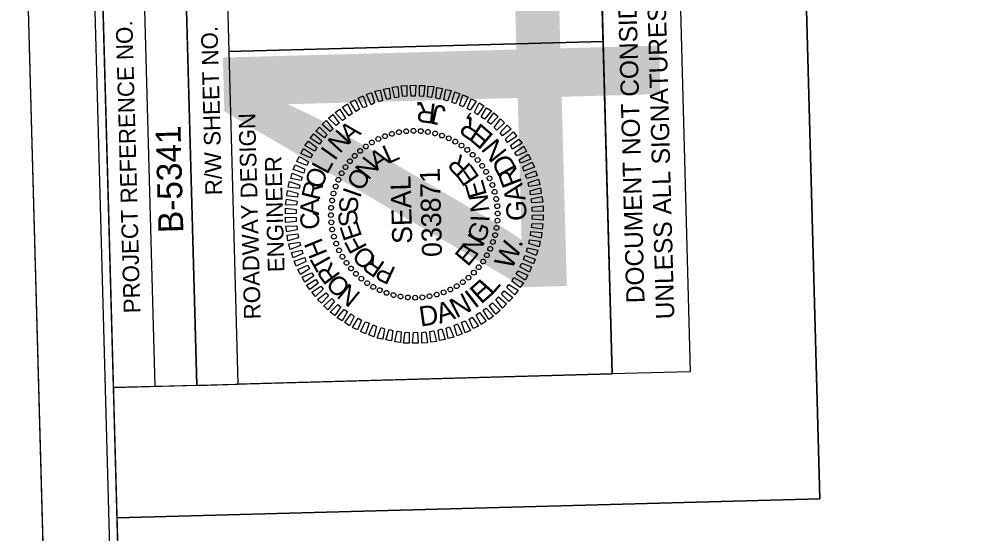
# Model space of a CAD drawing. Extents: x 1835283 to 1836442, y 993567 to 997230.
# Drawn here: x 1835301.2 to 1835586.3, y 995091.9 to 995246.4 of the extents above; entities that cross this region are included whole.
import ezdxf

# ---------------------------------------------------------------- set-up
doc = ezdxf.new("R2010")
doc.units = 0
for name, color, linetype in [('Sheet Clip Boundary CELL', 7, 'Continuous'), ('Sheet Cutting Line CELL', 7, 'Continuous'), ('Sheet Data Field CELL', 7, 'Continuous'), ('Sheet Layout Plan Border', 7, 'Continuous'), ('Sheet PE Seal Cell', 7, 'Continuous'), ('Sheet Plan CELL', 7, 'Continuous'), ('Sheet Plan Layout CELL', 7, 'Continuous'), ('Sheet Plot Border Inside CELL', 7, 'Continuous'), ('Sheet Plot Border Outside CELL', 7, 'Continuous'), ('Sheet Sticker Exception Certification CELL', 7, 'Continuous')]:
    doc.layers.add(name, color=color, linetype=linetype)

msp = doc.modelspace()

# ---------------------------------------------------------------- linework, layer by layer
at = {"layer": 'Sheet Clip Boundary CELL'}
msp.add_lwpolyline([(1836414.25, 993881.51), (1836374.18, 995348.6), (1835535.98, 995325.71), (1835542.09, 995102.18), (1835330.68, 995096.4), (1835364.64, 993852.84)], close=True, dxfattribs=at)
msp.add_lwpolyline([(1836414.25, 993881.51), (1836374.18, 995348.6), (1835535.98, 995325.71), (1835542.09, 995102.18), (1835330.68, 995096.4), (1835364.64, 993852.84)], close=True, dxfattribs=at)
at = {"layer": 'Sheet Cutting Line CELL'}
msp.add_line((1835301.2, 995351.94), (1835347.16, 993669.07), dxfattribs=at)
at = {"layer": 'Sheet Layout Plan Border'}
msp.add_lwpolyline([(1836414.25, 993881.51), (1836374.18, 995348.6), (1835535.98, 995325.71), (1835542.09, 995102.18), (1835330.68, 995096.4), (1835364.64, 993852.84)], close=True, dxfattribs=at)
msp.add_lwpolyline([(1836414.25, 993881.51), (1836374.18, 995348.6), (1835535.98, 995325.71), (1835542.09, 995102.18), (1835330.68, 995096.4), (1835364.64, 993852.84)], close=True, dxfattribs=at)
at = {"layer": 'Sheet PE Seal Cell'}
for p, q in [((1835409.28, 995210.37), (1835409.28, 995210.37)), ((1835411.25, 995211.22), (1835411.25, 995211.22)), ((1835413.34, 995211.88), (1835413.34, 995211.88)), ((1835415.52, 995212.34), (1835415.52, 995212.34)), ((1835417.67, 995212.7), (1835417.67, 995212.7)), ((1835419.86, 995212.81), (1835419.86, 995212.81)), ((1835422.07, 995212.72), (1835422.07, 995212.72)), ((1835424.22, 995212.43), (1835424.22, 995212.43)), ((1835426.34, 995212.04), (1835426.34, 995212.04)), ((1835428.45, 995211.39), (1835428.45, 995211.39)), ((1835430.48, 995210.55), (1835430.48, 995210.55)), ((1835405.49, 995208.12), (1835405.49, 995208.12)), ((1835407.35, 995209.32), (1835407.35, 995209.32)), ((1835432.46, 995209.6), (1835432.46, 995209.6)), ((1835434.29, 995208.4), (1835434.29, 995208.4)), ((1835402.16, 995205.27), (1835402.16, 995205.27)), ((1835403.77, 995206.82), (1835403.77, 995206.82)), ((1835436.07, 995207.1), (1835436.07, 995207.1)), ((1835437.67, 995205.64), (1835437.67, 995205.64)), ((1835399.4, 995201.9), (1835399.4, 995201.9)), ((1835400.7, 995203.68), (1835400.7, 995203.68)), ((1835439.21, 995204.03), (1835439.21, 995204.03)), ((1835440.51, 995202.32), (1835440.51, 995202.32)), ((1835398.2, 995200.06), (1835398.2, 995200.06)), ((1835441.71, 995200.45), (1835441.71, 995200.45)), ((1835396.41, 995196.06), (1835396.41, 995196.06)), ((1835397.26, 995198.09), (1835397.26, 995198.09)), ((1835442.76, 995198.53), (1835442.76, 995198.53)), ((1835443.62, 995196.55), (1835443.62, 995196.55)), ((1835395.77, 995193.94), (1835395.77, 995193.94)), ((1835444.27, 995194.47), (1835444.27, 995194.47)), ((1835395.38, 995191.83), (1835395.38, 995191.83)), ((1835444.73, 995192.28), (1835444.73, 995192.28)), ((1835395, 995187.47), (1835395, 995187.47)), ((1835395.09, 995189.67), (1835395.09, 995189.67)), ((1835420.1, 995187.71), (1835420.1, 995187.71)), ((1835445.09, 995190.14), (1835445.09, 995190.14)), ((1835445.2, 995187.94), (1835445.2, 995187.94)), ((1835395.11, 995185.27), (1835395.11, 995185.27)), ((1835445.11, 995185.74), (1835445.11, 995185.74)), ((1835395.46, 995183.13), (1835395.46, 995183.13)), ((1835444.82, 995183.58), (1835444.82, 995183.58)), ((1835395.92, 995180.94), (1835395.92, 995180.94)), ((1835396.58, 995178.86), (1835396.58, 995178.86)), ((1835443.79, 995179.35), (1835443.79, 995179.35)), ((1835444.43, 995181.47), (1835444.43, 995181.47)), ((1835397.44, 995176.88), (1835397.44, 995176.88)), ((1835442.94, 995177.33), (1835442.94, 995177.33)), ((1835398.49, 995174.96), (1835398.49, 995174.96)), ((1835399.69, 995173.09), (1835399.69, 995173.09)), ((1835440.79, 995173.52), (1835440.79, 995173.52)), ((1835441.99, 995175.35), (1835441.99, 995175.35)), ((1835400.99, 995171.38), (1835400.99, 995171.38)), ((1835439.49, 995171.73), (1835439.49, 995171.73)), ((1835402.53, 995169.77), (1835402.53, 995169.77)), ((1835404.12, 995168.31), (1835404.12, 995168.31)), ((1835436.43, 995168.6), (1835436.43, 995168.6)), ((1835438.03, 995170.14), (1835438.03, 995170.14)), ((1835405.91, 995167.01), (1835405.91, 995167.01)), ((1835407.74, 995165.81), (1835407.74, 995165.81)), ((1835409.72, 995164.86), (1835409.72, 995164.86)), ((1835430.92, 995165.04), (1835430.92, 995165.04)), ((1835432.84, 995166.1), (1835432.84, 995166.1)), ((1835434.71, 995167.3), (1835434.71, 995167.3)), ((1835411.74, 995164.02), (1835411.74, 995164.02)), ((1835413.86, 995163.38), (1835413.86, 995163.38)), ((1835415.97, 995162.98), (1835415.97, 995162.98)), ((1835418.13, 995162.69), (1835418.13, 995162.69)), ((1835420.33, 995162.6), (1835420.33, 995162.6)), ((1835422.53, 995162.71), (1835422.53, 995162.71)), ((1835424.67, 995163.07), (1835424.67, 995163.07)), ((1835426.86, 995163.53), (1835426.86, 995163.53)), ((1835428.94, 995164.19), (1835428.94, 995164.19))]:
    msp.add_line(p, q, dxfattribs=at)
for points in [[(1835409.47, 995221.53), (1835408.23, 995224.7), (1835409.88, 995225.04), (1835410.51, 995221.91)], [(1835411.85, 995222.19), (1835410.82, 995225.32), (1835412.51, 995225.66), (1835412.9, 995222.52)], [(1835414.24, 995222.71), (1835413.45, 995225.94), (1835415.15, 995226.14), (1835415.43, 995222.94)], [(1835416.63, 995223.08), (1835416.14, 995226.31), (1835417.84, 995226.46), (1835417.83, 995223.21)], [(1835419.13, 995223.19), (1835418.89, 995226.44), (1835420.59, 995226.48), (1835420.33, 995223.23)], [(1835421.63, 995223.21), (1835421.64, 995226.46), (1835423.29, 995226.41), (1835422.83, 995223.14)], [(1835424.04, 995223.03), (1835424.25, 995226.23), (1835425.95, 995226.08), (1835425.24, 995222.81)], [(1835426.6, 995222.7), (1835426.91, 995225.81), (1835428.62, 995225.5), (1835427.66, 995222.33)], [(1835429.01, 995222.11), (1835429.58, 995225.23), (1835431.24, 995224.92), (1835430.07, 995221.74)], [(1835431.43, 995221.43), (1835432.25, 995224.55), (1835433.81, 995223.94), (1835432.5, 995220.91)], [(1835402.65, 995218.64), (1835400.82, 995221.39), (1835402.35, 995222.08), (1835403.58, 995219.27)], [(1835404.77, 995219.7), (1835403.19, 995222.61), (1835404.77, 995223.3), (1835405.86, 995220.23)], [(1835407.09, 995220.66), (1835405.71, 995223.68), (1835407.25, 995224.27), (1835408.13, 995221.19)], [(1835433.66, 995220.49), (1835434.72, 995223.62), (1835436.29, 995222.91), (1835434.77, 995220.02)], [(1835435.98, 995219.55), (1835437.16, 995222.44), (1835438.73, 995221.73), (1835436.95, 995218.98)], [(1835398.47, 995215.93), (1835396.3, 995218.32), (1835397.73, 995219.31), (1835399.4, 995216.55)], [(1835400.48, 995217.28), (1835398.51, 995219.88), (1835399.99, 995220.87), (1835401.46, 995218.01)], [(1835438.17, 995218.41), (1835439.59, 995221.25), (1835441.02, 995220.29), (1835439.09, 995217.64)], [(1835440.21, 995216.97), (1835441.83, 995219.71), (1835443.31, 995218.8), (1835441.17, 995216.34)], [(1835394.81, 995212.58), (1835392.4, 995214.66), (1835393.57, 995215.89), (1835395.59, 995213.35)], [(1835396.56, 995214.37), (1835394.25, 995216.61), (1835395.57, 995217.7), (1835397.54, 995215.1)], [(1835442.15, 995215.52), (1835444.03, 995218.17), (1835445.36, 995217.11), (1835443.07, 995214.84)], [(1835444.09, 995213.82), (1835446.07, 995216.43), (1835447.26, 995215.21), (1835444.92, 995213.04)], [(1835393.11, 995210.73), (1835390.45, 995212.71), (1835391.62, 995213.94), (1835393.83, 995211.7)], [(1835445.89, 995212.22), (1835448.03, 995214.48), (1835449.26, 995213.31), (1835446.61, 995211.29)], [(1835391.61, 995208.79), (1835388.81, 995210.56), (1835389.88, 995211.89), (1835392.29, 995209.76)], [(1835447.49, 995210.26), (1835449.83, 995212.48), (1835450.92, 995211.16), (1835448.17, 995209.33)], [(1835449.04, 995208.4), (1835451.54, 995210.32), (1835452.53, 995209.05), (1835449.67, 995207.32)], [(1835388.87, 995204.71), (1835385.99, 995205.98), (1835386.8, 995207.5), (1835389.45, 995205.68)], [(1835390.17, 995206.7), (1835387.22, 995208.37), (1835388.24, 995209.69), (1835390.74, 995207.81)], [(1835450.35, 995206.24), (1835453, 995208.16), (1835453.84, 995206.63), (1835450.98, 995205.31)], [(1835387.79, 995202.38), (1835384.8, 995203.55), (1835385.46, 995205.12), (1835388.31, 995203.49)], [(1835451.61, 995204.12), (1835454.37, 995205.8), (1835455.11, 995204.27), (1835452.09, 995203.04)], [(1835386.9, 995200.1), (1835383.72, 995201.17), (1835384.28, 995202.58), (1835387.22, 995201.26)], [(1835452.72, 995201.95), (1835455.58, 995203.33), (1835456.23, 995201.85), (1835453.06, 995200.71)], [(1835386.06, 995197.83), (1835382.94, 995198.5), (1835383.4, 995200.06), (1835386.38, 995198.89)], [(1835453.59, 995199.53), (1835456.56, 995200.76), (1835457.05, 995199.22), (1835453.97, 995198.49)], [(1835385.47, 995195.41), (1835382.21, 995195.83), (1835382.57, 995197.54), (1835385.7, 995196.47)], [(1835454.3, 995197.14), (1835457.42, 995198.28), (1835457.82, 995196.59), (1835454.58, 995196.1)], [(1835384.99, 995192.85), (1835381.78, 995193.21), (1835381.99, 995194.87), (1835385.11, 995194.05)], [(1835454.92, 995194.76), (1835458.1, 995195.65), (1835458.29, 995194), (1835455.1, 995193.56)], [(1835384.66, 995190.44), (1835381.41, 995190.55), (1835381.66, 995192.21), (1835384.83, 995191.65)], [(1835455.28, 995192.37), (1835458.47, 995193.01), (1835458.71, 995191.31), (1835455.47, 995191.17)], [(1835455.6, 995189.88), (1835458.84, 995190.22), (1835458.84, 995188.56), (1835455.58, 995188.68)], [(1835384.58, 995187.94), (1835381.33, 995187.85), (1835381.33, 995189.5), (1835384.6, 995189.14)], [(1835455.62, 995187.48), (1835458.87, 995187.56), (1835458.86, 995185.91), (1835455.6, 995186.28)], [(1835384.59, 995185.54), (1835381.35, 995185.2), (1835381.36, 995186.85), (1835384.61, 995186.74)], [(1835455.54, 995184.97), (1835458.79, 995184.86), (1835458.54, 995183.2), (1835455.37, 995183.77)], [(1835384.91, 995183.04), (1835381.73, 995182.41), (1835381.48, 995184.1), (1835384.73, 995184.24)], [(1835385.28, 995180.65), (1835382.1, 995179.77), (1835381.91, 995181.41), (1835385.1, 995181.85)], [(1835455.2, 995182.56), (1835458.41, 995182.2), (1835458.21, 995180.54), (1835455.08, 995181.36)], [(1835385.89, 995178.27), (1835382.77, 995177.13), (1835382.38, 995178.82), (1835385.61, 995179.31)], [(1835454.72, 995180), (1835457.98, 995179.59), (1835457.63, 995177.88), (1835454.5, 995178.94)], [(1835386.61, 995175.89), (1835383.64, 995174.66), (1835383.15, 995176.19), (1835386.23, 995176.93)], [(1835454.14, 995177.58), (1835457.26, 995176.92), (1835456.8, 995175.35), (1835453.82, 995176.52)], [(1835387.48, 995173.46), (1835384.61, 995172.08), (1835383.97, 995173.57), (1835387.14, 995174.7)], [(1835453.3, 995175.31), (1835456.48, 995174.24), (1835455.92, 995172.83), (1835452.98, 995174.15)], [(1835388.58, 995171.29), (1835385.83, 995169.61), (1835385.09, 995171.14), (1835388.1, 995172.38)], [(1835451.32, 995170.7), (1835454.21, 995169.43), (1835453.4, 995167.91), (1835450.75, 995169.74)], [(1835452.41, 995173.03), (1835455.39, 995171.86), (1835454.74, 995170.3), (1835451.89, 995171.92)], [(1835389.84, 995169.17), (1835387.19, 995167.25), (1835386.35, 995168.78), (1835389.22, 995170.11)], [(1835391.15, 995167.01), (1835388.65, 995165.09), (1835387.67, 995166.36), (1835390.52, 995168.09)], [(1835450.03, 995168.72), (1835452.97, 995167.05), (1835451.96, 995165.72), (1835449.46, 995167.6)], [(1835392.7, 995165.15), (1835390.36, 995162.94), (1835389.28, 995164.26), (1835392.03, 995166.08)], [(1835447.09, 995164.68), (1835449.74, 995162.71), (1835448.58, 995161.47), (1835446.36, 995163.71)], [(1835448.58, 995166.63), (1835451.38, 995164.85), (1835450.32, 995163.52), (1835447.91, 995165.66)], [(1835394.31, 995163.19), (1835392.17, 995160.93), (1835390.94, 995162.1), (1835393.58, 995164.12)], [(1835396.1, 995161.59), (1835394.12, 995158.99), (1835392.94, 995160.2), (1835395.28, 995162.37)], [(1835445.39, 995162.84), (1835447.79, 995160.75), (1835446.63, 995159.52), (1835444.61, 995162.07)], [(1835398.05, 995159.89), (1835396.17, 995157.24), (1835394.84, 995158.31), (1835397.13, 995160.57)], [(1835399.99, 995158.45), (1835398.36, 995155.7), (1835396.89, 995156.61), (1835399.02, 995159.07)], [(1835441.73, 995159.49), (1835443.89, 995157.09), (1835442.47, 995156.11), (1835440.79, 995158.86)], [(1835443.64, 995161.04), (1835445.95, 995158.8), (1835444.63, 995157.71), (1835442.65, 995160.31)], [(1835402.03, 995157), (1835400.61, 995154.16), (1835399.18, 995155.12), (1835401.11, 995157.78)], [(1835404.21, 995155.86), (1835403.04, 995152.98), (1835401.47, 995153.69), (1835403.25, 995156.43)], [(1835437.55, 995156.77), (1835439.38, 995154.02), (1835437.84, 995153.33), (1835436.62, 995156.15)], [(1835439.71, 995158.13), (1835441.68, 995155.53), (1835440.21, 995154.54), (1835438.73, 995157.4)], [(1835406.54, 995154.92), (1835405.47, 995151.79), (1835403.9, 995152.5), (1835405.42, 995155.39)], [(1835408.76, 995153.98), (1835407.95, 995150.86), (1835406.38, 995151.47), (1835407.7, 995154.51)], [(1835411.18, 995153.3), (1835410.62, 995150.18), (1835408.96, 995150.49), (1835410.12, 995153.67)], [(1835428.34, 995153.22), (1835429.38, 995150.1), (1835427.69, 995149.75), (1835427.3, 995152.89)], [(1835430.73, 995153.88), (1835431.96, 995150.72), (1835430.32, 995150.37), (1835429.69, 995153.51)], [(1835433.1, 995154.75), (1835434.49, 995151.74), (1835432.95, 995151.14), (1835432.07, 995154.22)], [(1835435.43, 995155.71), (1835437.01, 995152.81), (1835435.43, 995152.11), (1835434.34, 995155.18)], [(1835413.6, 995152.72), (1835413.29, 995149.61), (1835411.58, 995149.91), (1835412.54, 995153.09)], [(1835416.16, 995152.39), (1835415.95, 995149.18), (1835414.24, 995149.33), (1835414.95, 995152.6)], [(1835418.57, 995152.2), (1835418.56, 995148.95), (1835416.9, 995149), (1835417.36, 995152.27)], [(1835421.07, 995152.22), (1835421.31, 995148.98), (1835419.61, 995148.93), (1835419.87, 995152.19)], [(1835423.57, 995152.34), (1835424.05, 995149.1), (1835422.36, 995148.95), (1835422.37, 995152.21)], [(1835425.96, 995152.7), (1835426.74, 995149.47), (1835425.05, 995149.28), (1835424.76, 995152.47)]]:
    msp.add_lwpolyline(points, close=True, dxfattribs=at)
for centre, major_axis in [((1835415.5, 995212.36), (-0.132, 0.708)), ((1835417.67, 995212.67), (-0.07, 0.717)), ((1835419.85, 995212.79), (-0.007, 0.72)), ((1835422.04, 995212.71), (0.056, 0.718)), ((1835424.21, 995212.45), (0.118, 0.71)), ((1835409.28, 995210.33), (-0.311, 0.65)), ((1835411.29, 995211.19), (-0.253, 0.674)), ((1835413.37, 995211.87), (-0.193, 0.694)), ((1835426.35, 995211.99), (0.179, 0.697)), ((1835428.44, 995211.36), (0.24, 0.679)), ((1835430.47, 995210.54), (0.298, 0.656)), ((1835432.42, 995209.55), (0.354, 0.627)), ((1835403.79, 995206.76), (-0.468, 0.547)), ((1835405.51, 995208.11), (-0.419, 0.586)), ((1835407.34, 995209.3), (-0.366, 0.62)), ((1835434.28, 995208.39), (0.407, 0.594)), ((1835436.03, 995207.08), (0.457, 0.556)), ((1835402.19, 995205.27), (-0.514, 0.504)), ((1835437.66, 995205.61), (0.504, 0.514)), ((1835439.15, 995204.02), (0.547, 0.468)), ((1835399.41, 995201.89), (-0.594, 0.407)), ((1835400.73, 995203.64), (-0.556, 0.457)), ((1835440.5, 995202.29), (0.586, 0.419)), ((1835397.26, 995198.08), (-0.656, 0.298)), ((1835398.26, 995200.03), (-0.627, 0.354)), ((1835441.69, 995200.46), (0.62, 0.366)), ((1835442.72, 995198.53), (0.65, 0.311)), ((1835396.45, 995196.05), (-0.679, 0.24)), ((1835443.58, 995196.52), (0.674, 0.253)), ((1835395.81, 995193.96), (-0.697, 0.179)), ((1835444.26, 995194.44), (0.694, 0.193)), ((1835444.75, 995192.3), (0.708, 0.132)), ((1835395.09, 995189.65), (-0.718, 0.056)), ((1835395.36, 995191.82), (-0.71, 0.118)), ((1835445.06, 995190.14), (0.717, 0.07)), ((1835395.02, 995187.46), (-0.72, -0.007)), ((1835445.18, 995187.95), (0.72, 0.007)), ((1835395.14, 995185.27), (-0.717, -0.07)), ((1835445.1, 995185.77), (0.718, -0.056)), ((1835395.44, 995183.11), (-0.708, -0.132)), ((1835395.94, 995180.98), (-0.694, -0.193)), ((1835444.39, 995181.45), (0.697, -0.179)), ((1835444.84, 995183.59), (0.71, -0.118)), ((1835396.62, 995178.9), (-0.674, -0.253)), ((1835443.75, 995179.36), (0.679, -0.24)), ((1835397.47, 995176.88), (-0.65, -0.311)), ((1835441.94, 995175.38), (0.627, -0.354)), ((1835442.93, 995177.33), (0.656, -0.298)), ((1835398.5, 995174.95), (-0.62, -0.366)), ((1835399.7, 995173.12), (-0.586, -0.419)), ((1835440.78, 995173.52), (0.594, -0.407)), ((1835401.05, 995171.4), (-0.547, -0.468)), ((1835402.54, 995169.8), (-0.504, -0.514)), ((1835438.01, 995170.15), (0.514, -0.504)), ((1835439.47, 995171.78), (0.556, -0.457)), ((1835404.17, 995168.34), (-0.457, -0.556)), ((1835405.92, 995167.02), (-0.407, -0.594)), ((1835434.69, 995167.3), (0.419, -0.586)), ((1835436.41, 995168.65), (0.468, -0.547)), ((1835407.77, 995165.86), (-0.354, -0.627)), ((1835409.72, 995164.87), (-0.298, -0.656)), ((1835411.75, 995164.06), (-0.24, -0.679)), ((1835428.91, 995164.22), (0.253, -0.674)), ((1835430.92, 995165.08), (0.311, -0.65)), ((1835432.85, 995166.11), (0.366, -0.62)), ((1835413.85, 995163.42), (-0.179, -0.697)), ((1835415.99, 995162.97), (-0.118, -0.71)), ((1835418.16, 995162.7), (-0.056, -0.718)), ((1835420.35, 995162.63), (0.007, -0.72)), ((1835422.53, 995162.74), (0.07, -0.717)), ((1835424.7, 995163.05), (0.132, -0.708)), ((1835426.83, 995163.55), (0.193, -0.694))]:
    msp.add_ellipse(centre, major_axis=major_axis, ratio=0.999708, dxfattribs=at)
at = {"layer": 'Sheet Plan CELL'}
for p, q in [((1835342.14, 995135.92), (1835336.69, 995335.89)), ((1835354.67, 995136.27), (1835349.19, 995336.24)), ((1835354.67, 995136.27), (1835349.19, 995336.24)), ((1835364.42, 995236.63), (1835476.84, 995239.71)), ((1835354.67, 995136.27), (1835367.16, 995136.61))]:
    msp.add_line(p, q, dxfattribs=at)
for points in [[(1835324.15, 995335.59), (1835365.1, 993836.11), (1836414.7, 993864.77), (1836373.75, 995364.23)], [(1836414.7, 993864.77), (1835365.12, 993836.09), (1835329.59, 995135.59), (1835479.6, 995139.7), (1835474.15, 995339.66), (1836373.75, 995364.23)], [(1835364.42, 995236.63), (1835361.68, 995336.58), (1835474.15, 995339.66), (1835476.9, 995239.7)], [(1835329.59, 995135.59), (1835324.15, 995335.59), (1835349.19, 995336.24), (1835354.67, 995136.27)], [(1835367.16, 995136.61), (1835364.42, 995236.63), (1835476.9, 995239.7), (1835479.6, 995139.7)]]:
    msp.add_lwpolyline(points, close=True, dxfattribs=at)
at = {"layer": 'Sheet Plan Layout CELL'}
for points in [[(1835365.12, 993836.1), (1836414.7, 993864.79), (1836373.75, 995364.23), (1835535.55, 995341.34), (1835542.09, 995102.18), (1835330.68, 995096.4)], [(1835542.09, 995102.18), (1835535.55, 995341.36), (1835324.14, 995335.61), (1835330.68, 995096.4)]]:
    msp.add_lwpolyline(points, close=True, dxfattribs=at)
at = {"layer": 'Sheet Plot Border Inside CELL'}
msp.add_lwpolyline([(1836421.41, 993711.41), (1836375.91, 995376.78), (1835321.32, 995347.99), (1835366.8, 993682.61)], close=True, dxfattribs=at)
at = {"layer": 'Sheet Plot Border Outside CELL'}
msp.add_lwpolyline([(1836441.75, 993698.96), (1836395.79, 995381.84), (1835301.2, 995351.94), (1835347.16, 993669.07)], close=True, dxfattribs=at)
at = {"layer": 'Sheet Sticker Exception Certification CELL'}
for p, q in [((1835479.61, 995139.7), (1835474.15, 995339.66)), ((1835497.64, 995340.3), (1835503.1, 995140.34)), ((1835503.1, 995140.34), (1835479.61, 995139.7))]:
    msp.add_line(p, q, dxfattribs=at)

# ---------------------------------------------------------------- texts
at = {"layer": 'Sheet Data Field CELL'}
msp.add_text('B-5341', height=7.5, rotation=91.5643, dxfattribs=at).set_placement((1835350.66, 995182.15))
at = {"layer": 'Sheet PE Seal Cell'}
for s, height, rotation, p in [('.', 6, 180.8885, (1835422.48, 995221.45)), ('R', 6, 173.4083, (1835426.85, 995220.85)), ('J', 6, 168.1505, (1835429.86, 995220.09)), ('R', 6, 146.4361, (1835441.15, 995214.18)), (',', 6, 153.9163, (1835437.52, 995216.7)), ('N', 5.64, 47.3832, (1835397.7, 995205.75)), ('A', 5.64, 40.1815, (1835400.57, 995208.78)), ('E', 6, 139.3267, (1835444.27, 995211.37)), ('N', 6, 128.6009, (1835448.25, 995206.46)), ('I', 5.64, 54.5845, (1835396.21, 995203.56)), ('L', 5.64, 23.9652, (1835412.23, 995202.75)), ('N', 5.64, 52.0409, (1835406.32, 995197.78)), ('A', 5.64, 33.3246, (1835408.84, 995200.7)), ('R', 5.64, 134.0457, (1835437.46, 995202.29)), ('D', 6, 118.7251, (1835451.05, 995201.36)), ('L', 5.64, 61.7852, (1835393.92, 995199.45)), ('E', 5.64, 124.6884, (1835439.9, 995198.8)), ('R', 6, 111.2448, (1835452.56, 995197.21)), ('O', 5.64, 68.9855, (1835392.19, 995195)), ('O', 5.64, 61.3978, (1835404.41, 995194.38)), ('SEAL', 5.998, 91.5643, (1835419.49, 995178.89)), ('033871', 5.998, 91.5643, (1835428.46, 995174.96)), ('R', 5.64, 76.1854, (1835391.53, 995191.63)), ('E', 5.64, 105.9761, (1835442, 995193.56)), ('A', 6, 102.4045, (1835453.64, 995192.11)), ('I', 5.64, 70.7539, (1835403.77, 995192.36)), ('N', 5.64, 96.6207, (1835442.73, 995188.62)), ('A', 5.64, 90.5847, (1835391.45, 995187.42)), ('S', 5.64, 89.4647, (1835403.18, 995188.04)), ('G', 6, 91.6787, (1835453.87, 995185.79)), ('C', 5.64, 97.7842, (1835391.85, 995183.48)), ('S', 5.64, 98.8199, (1835403.33, 995184.45)), ('E', 5.64, 108.1754, (1835404.47, 995181.03)), ('G', 5.64, 68.5546, (1835440.95, 995178.67)), ('I', 5.64, 87.2655, (1835442.67, 995185.27)), ('N', 5.64, 59.1983, (1835438.81, 995174.81)), ('H', 5.64, 112.1838, (1835394.06, 995175.94)), ('F', 5.64, 117.5314, (1835406.06, 995177.87)), ('E', 5.64, 49.8412, (1835436.19, 995171.74)), ('W', 6, 64.9105, (1835449.39, 995170.79)), ('.', 6, 77.4446, (1835452.36, 995177.55)), ('O', 5.64, 136.2456, (1835409.1, 995174.65)), ('T', 5.64, 119.3841, (1835395.8, 995172.74)), ('R', 5.64, 126.5848, (1835398.09, 995169.4)), ('R', 5.64, 145.604, (1835411.6, 995172.97)), ('P', 5.64, 154.9632, (1835414.84, 995171.46)), ('O', 5.64, 133.7861, (1835401.28, 995166.03)), ('E', 6, 41.326, (1835440.17, 995160.48)), ('L', 6, 48.4354, (1835443.39, 995163.17)), ('N', 5.64, 140.9878, (1835404.24, 995163.81)), ('I', 6, 37.5241, (1835438.32, 995159.21)), ('N', 6, 26.7983, (1835432.7, 995156.32)), ('D', 6, 8.0822, (1835421.96, 995153.93)), ('A', 6, 17.958, (1835427.73, 995154.75))]:
    msp.add_text(s, height=height, rotation=rotation, dxfattribs=at).set_placement(p)
at = {"layer": 'Sheet Plan CELL'}
for s, height, p in [('PROJECT REFERENCE NO.', 5.0001, (1835337.71, 995158.02)), ('R/W SHEET NO.', 5.0001, (1835362.3, 995193.5)), ('ROADWAY DESIGN', 5.0001, (1835373.92, 995156.18)), ('ENGINEER', 5, (1835381.08, 995170.37))]:
    msp.add_text(s, height=height, rotation=91.5643, dxfattribs=at).set_placement(p)
at = {"layer": 'Sheet Plan Layout CELL'}
msp.add_text('4', height=131.25, rotation=91.5643, dxfattribs=at).set_placement((1835495.79, 995162.94))
at = {"layer": 'Sheet Sticker Exception Certification CELL'}
for s, p in [('UNLESS ALL SIGNATURES COMPLETED', (1835498.32, 995156.21)), ('DOCUMENT NOT CONSIDERED FINAL', (1835489.38, 995161.04))]:
    msp.add_text(s, height=5.5, rotation=91.5643, dxfattribs=at).set_placement(p)

doc.saveas('drawing.dxf')
